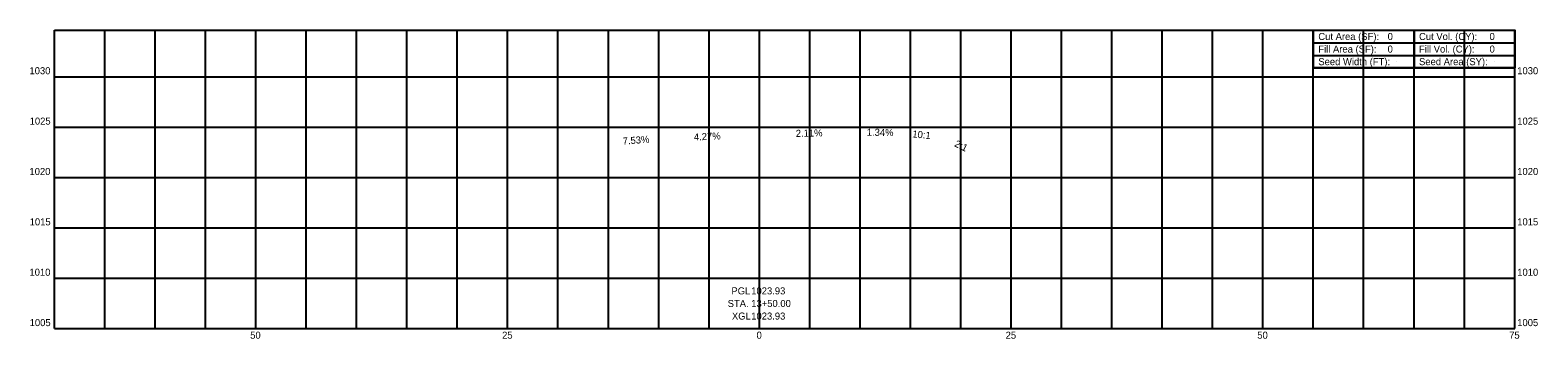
# Model space of a CAD drawing. Extents: x -72 to 77, y 1004 to 1035.
import ezdxf

# ---------------------------------------------------------------- set-up
doc = ezdxf.new("R2010")
doc.units = 0
for name, color, linetype in [('Default', 7, 'Continuous'), ('SH_Data', 7, 'Continuous'), ('SH_Major_Grid_Line', 7, 'Continuous'), ('SH_Masking', 7, 'Continuous'), ('SH_Text', 7, 'Continuous')]:
    doc.layers.add(name, color=color, linetype=linetype)

msp = doc.modelspace()

# ---------------------------------------------------------------- linework, layer by layer
at = {"layer": 'Default'}
msp.add_circle((75, 1034.62), 0.000417, dxfattribs=at)
msp.add_circle((75, 1034.62), 0.000417, dxfattribs=at)
msp.add_circle((75, 1034.62), 0.000417, dxfattribs=at)
msp.add_circle((75, 1034.62), 0.000417, dxfattribs=at)
msp.add_circle((75, 1034.62), 0.000417, dxfattribs=at)
msp.add_circle((75, 1034.62), 0.000417, dxfattribs=at)
msp.add_circle((75, 1034.62), 0.000417, dxfattribs=at)
msp.add_circle((75, 1034.62), 0.000417, dxfattribs=at)
msp.add_circle((75, 1034.62), 0.000417, dxfattribs=at)
msp.add_circle((75, 1034.62), 0.000417, dxfattribs=at)
msp.add_circle((75, 1034.62), 0.000417, dxfattribs=at)
msp.add_circle((75, 1034.62), 0.000417, dxfattribs=at)
at = {"layer": 'SH_Data'}
for p, q in [((55, 1034.62), (75, 1034.62)), ((55, 1034.62), (55, 1032.12)), ((65, 1034.62), (65, 1030.87)), ((75, 1034.62), (75, 1032.12)), ((55, 1033.37), (75, 1033.37)), ((55, 1032.12), (75, 1032.12)), ((63.3, 1031.5), (63.3, 1031.5)), ((72.95, 1031.5), (72.95, 1031.5))]:
    msp.add_line(p, q, dxfattribs=at)
msp.add_lwpolyline([(55, 1032.12), (55, 1030.87), (75, 1030.87), (75, 1032.12)], dxfattribs=at)
at = {"layer": 'SH_Major_Grid_Line'}
for p, q in [((-70, 1034.62), (75, 1034.62)), ((-70, 1005), (-70, 1034.62)), ((-65, 1005), (-65, 1034.62)), ((-60, 1005), (-60, 1034.62)), ((-55, 1005), (-55, 1034.62)), ((-50, 1005), (-50, 1034.62)), ((-45, 1005), (-45, 1034.62)), ((-40, 1005), (-40, 1034.62)), ((-35, 1005), (-35, 1034.62)), ((-30, 1005), (-30, 1034.62)), ((-25, 1005), (-25, 1034.62)), ((-20, 1005), (-20, 1034.62)), ((-15, 1005), (-15, 1034.62)), ((-10, 1005), (-10, 1034.62)), ((-5, 1005), (-5, 1034.62)), ((0, 1005), (0, 1034.62)), ((5, 1005), (5, 1034.62)), ((10, 1005), (10, 1034.62)), ((15, 1005), (15, 1034.62)), ((20, 1005), (20, 1034.62)), ((25, 1005), (25, 1034.62)), ((30, 1005), (30, 1034.62)), ((35, 1005), (35, 1034.62)), ((40, 1005), (40, 1034.62)), ((45, 1005), (45, 1034.62)), ((50, 1005), (50, 1034.62)), ((55, 1005), (55, 1034.62)), ((60, 1005), (60, 1034.62)), ((65, 1005), (65, 1034.62)), ((70, 1005), (70, 1034.62)), ((75, 1005), (75, 1034.62)), ((-70, 1030), (75, 1030)), ((-70, 1025), (75, 1025)), ((-70, 1020), (75, 1020)), ((-70, 1015), (75, 1015)), ((-70, 1010), (75, 1010)), ((-70, 1005), (75, 1005))]:
    msp.add_line(p, q, dxfattribs=at)
at = {"layer": 'SH_Masking'}
msp.add_lwpolyline([(55, 1034.62), (75, 1034.62), (75, 1030.87), (55, 1030.87)], close=True, dxfattribs=at)

# ---------------------------------------------------------------- texts
at = {"layer": 'SH_Text'}
for s, p in [('Cut Area (SF):', (55.5, 1033.65)), ('Fill Area (SF):', (55.5, 1032.4)), ('0', (62.38, 1033.65)), ('0', (62.38, 1032.4)), ('Cut Vol. (CY):', (65.5, 1033.65)), ('Fill Vol. (CY):', (65.5, 1032.4)), ('0', (72.5, 1033.65)), ('0', (72.5, 1032.4)), ('Seed Width (FT):', (55.5, 1031.15)), ('Seed Area (SY):', (65.5, 1031.15)), ('1030', (-72.48, 1030.25)), ('1030', (75.25, 1030.25)), ('1025', (-72.46, 1025.25)), ('1025', (75.25, 1025.25)), ('1020', (-72.48, 1020.25)), ('1020', (75.25, 1020.25)), ('1015', (-72.46, 1015.25)), ('1015', (75.25, 1015.25)), ('1010', (-72.48, 1010.25)), ('1010', (75.25, 1010.25)), ('PGL ', (-2.78, 1008.4)), ('1023.93', (-0.81, 1008.4)), ('STA. 13+50.00', (-3.15, 1007.15)), ('XGL ', (-2.73, 1005.9)), ('1023.93', (-0.81, 1005.9)), ('1005', (-72.46, 1005.25)), ('50', (-50.56, 1004)), ('25', (-25.55, 1004)), ('0', (-0.28, 1004)), ('25', (24.45, 1004)), ('50', (49.44, 1004)), ('75', (74.45, 1004)), ('1005', (75.25, 1005.25))]:
    msp.add_text(s, height=0.7, dxfattribs=at).set_placement(p)
for s, rotation, p in [('7.53%', 4.3038, (-13.55, 1023.26)), ('4.27%', 2.4437, (-6.49, 1023.67)), ('2.11%', 1.2085, (3.62, 1024.03)), ('1.34%', 359.2295, (10.66, 1024.15)), ('10:1', 354.2882, (15.16, 1023.99)), ('10:1', 354.2882, (15.16, 1023.99)), ('10:1', 354.2882, (15.16, 1023.99)), ('2:1', 333.4352, (19.3, 1023.13))]:
    msp.add_text(s, height=0.7, rotation=rotation, dxfattribs=at).set_placement(p)

doc.saveas('drawing.dxf')
